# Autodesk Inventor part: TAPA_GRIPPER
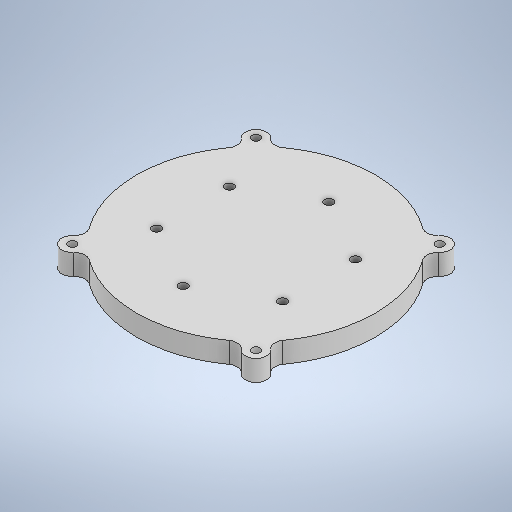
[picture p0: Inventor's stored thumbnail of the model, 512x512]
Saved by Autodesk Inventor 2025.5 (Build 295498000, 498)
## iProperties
Created: 2026-10
Part Number: TAPA_GRIPPER
Material: Genérico
Document SubType Name: Modeling
Designer: Luis MuÃ±oz
Density: 1 g/cm^3
Appearance: Valor por defecto
Project: TESIS 2 - Plataforma mecatrÃ³nica preventiva desacoplada
Description: Carcasa del módulo electrónico
Material_Fabricacion: PLA
Author: Luis M
Title: Carcasa del mÃ³dulo electrÃ³nico
Revision Number: 00
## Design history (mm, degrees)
sketch "Boceto1"
  geometry: L1 (5.6, 22)-(-5.6, 22); L2 (-5.6, 22)-(-5.6, -22); L3 (-5.6, -22)-(5.6, -22); L4 (5.6, -22)-(5.6, 22); L5 (5.6, 22)-(-5.6, -22); L6 (-5.6, 22)-(5.6, -22); L7 (0, 0)-(35, 0); L8 (35, 0)-(35, 40); L9 (35, 40)-(0, 40); L10 (0, 40)-(0, 0); L11 (35, 40)-(-27, 40); L12 (-27, 40)-(-27, -40); L13 (-27, -40)-(35, -40); L14 (35, -40)-(35, 40); C1 r 1.55 at (0, 0); C2 r 1.55 at (5.6, -22); C3 r 1.55 at (-5.6, -22); C4 r 1.55 at (5.6, 22); C5 r 1.55 at (-5.6, 22); C6 r 60.5 at (0, 0); C7 r 62.5 at (0, 0); C8 r 1.55 at (35, -40); C9 r 1.55 at (35, 40); C10 r 1.55 at (-27, 40); C11 r 1.55 at (-27, -40); 1 further point
  constraints: 28 end point, 11 centre point, 11 coincident, 6 parallel, 3 horizontal, 3 perpendicular, 2 midpoint
  dimensions: "d0" = 44 distance of L3.end L1.start; "d1" = 11.2 distance of L1.start L1.end; "d2" = 3.1 diameter of C1; "d3" = 3.1 diameter of C2; "d4" = 3.1 diameter of C3; "d5" = 3.1 diameter of C4; "d6" = 3.1 diameter of C5; "d7" = 121 diameter of C6; "d11" = 35 distance of L9.end L8.end; "d12" = 40 distance of L8.end L7.end; "d13" = 62 distance of L13.end L12.end; "d14" = 80 distance of L12.end L11.end; "d15" = 3.1 diameter of C8; "d16" = 3.1 diameter of C9; "d17" = 3.1 diameter of C10; "d18" = 3.1 diameter of C11
extrude "Extrusión1" new body sketch "Boceto1" distance "d9" = 6; taper "d10" = 0 deg
extrude "Extrusión2" cut sketch "Boceto1" distance "d19" = 5; taper "d20" = 0 deg
sketch "Boceto2"
  geometry: C1 r 1.55 at (27, -40) reference; C2 r 1.55 at (-35, -40) reference; C3 r 1.55 at (27, 40) reference; C4 r 1.55 at (-35, 40) reference; C5 r 60.5 at (0, 0) reference; C6 r 1.55 at (5.6, 22) reference; C7 r 1.55 at (5.6, -22) reference; C8 r 1.55 at (-5.6, -22) reference; C9 r 1.55 at (0, 0) reference; C10 r 1.55 at (-5.6, 22) reference; C11 r 57.5 at (0, 0); 1 further point
  constraints: 1 centre point, 1 coincident
  dimensions: "d21" = 115 diameter of C11
extrude "Extrusión3" join sketch "Boceto2" distance "d22" = 30; taper "d23" = 0 deg
sketch "Boceto5"
  geometry: L1 (-30, -57.5)-(-30, 57.5) reference; L2 (0, 57.5)-(0, -57.5) reference; L3 (0, 0)-(-12, 0); L4 (-7, 15)-(-17, 15); L5 (-17, 15)-(-17, -15); L6 (-17, -15)-(-7, -15); L7 (-7, -15)-(-7, 15); L8 (-7, 15)-(-17, -15); L9 (-17, 15)-(-7, -15); L10 (-12, 15)-(-12, -15)
  constraints: 16 end point, 4 midpoint, 2 horizontal, 2 parallel, 1 perpendicular
  dimensions: "d28" = 12 distance of L3.start L3.end; "d29" = 10 distance of L6.end L5.end; "d30" = 30 distance of L5.end L4.end
extrude "Extrusión5" cut sketch "Boceto5" stored distance "d31" = 181; taper "d32" = 0 deg
sketch "Boceto6"
  geometry: L1 (47.204, 44.298)-(42.204, 44.298); L2 (42.204, 44.298)-(42.204, -44.298); L3 (42.204, -44.298)-(47.204, -44.298); L4 (47.204, -44.298)-(47.204, 44.298); L5 (47.204, 44.298)-(42.204, -44.298); L6 (42.204, 44.298)-(47.204, -44.298); C1 r 60.5 at (0, 0) reference; C2 r 1.55 at (5.6, -22) reference; C3 r 1.55 at (5.6, 22) reference; C4 r 1.55 at (-5.6, 22) reference; C5 r 1.55 at (0, 0) reference; C6 r 1.55 at (-5.6, -22) reference; 6 further points
  constraints: 12 end point, 2 midpoint, 2 parallel, 1 horizontal, 1 perpendicular
  dimensions: "d33" = 5 distance of L3.end L2.end
extrude "Extrusión6" join sketch "Boceto6" distance "d34" = 25; taper "d35" = 0 deg
node "Plano de trabajo1"
sketch "Boceto7"
  geometry: L1 (87.646, 4.924)-(0.949, 4.924) reference; L2 (6.455, 0)-(82.14, 0) reference; L3 (6.455, 0)-(82.14, 0); L4 (82.14, 0)-(82.14, -10); L5 (82.14, -10)-(6.455, -10); L6 (6.455, -10)-(6.455, 0); L7 (44.298, -10)-(44.298, 0); L8 (66.798, -5)-(21.798, -5); C1 r 1.6 at (21.798, -5); C2 r 1.6 at (66.798, -5); 11 further points; 3 other entities
  constraints: 12 end point, 4 midpoint, 2 centre point, 2 coincident, 2 horizontal, 2 parallel, 1 perpendicular, 4 other
  dimensions: "d37" = 10 distance of L3.end L4.end; "d38" = 45 distance of L8.start L8.end; "d39" = 3.2 diameter of C1; "d40" = 3.2 diameter of C2
extrude "Extrusión7" join sketch "Boceto7" distance "d41" = 4; taper "d42" = 0 deg
fillet "Empalme3" dims "d45" = 4
sketch "Boceto8"
  geometry: L1 (-40, 50)-(40, 50); L2 (40, 50)-(40, -50); L3 (40, -50)-(-40, -50); L4 (-40, -50)-(-40, 50); L5 (-40, 50)-(40, -50); L6 (40, 50)-(-40, -50); L7 (48.099, 51.331)-(38.216, 40.784); L8 (38.216, 40.784)-(40.703, 59.935); L9 (40.703, 59.935)-(31.476, 46.348); L10 (47.613, -50.812)-(37.845, -40.388); L11 (30.656, -46.324)-(43.643, -62.557); L12 (-42.321, -62.318)-(-29.416, -43.314); L13 (-52.517, -56.045)-(-40, -42.688); L14 (-42.805, 60.306)-(-29.501, 46.108); L15 (-37.445, 39.961)-(-48.012, 51.238); C1 r 60.5 at (0, 0) reference; C2 r 57.5 at (0, 0) reference; C3 r 1.55 at (0, 0) reference; C4 r 2 at (40, 50); C5 r 2 at (40, -50); C6 r 2 at (-40, -50); C7 r 2 at (-40, 50); C8 r 5 at (40, 50); C9 r 5 at (40, -50); C10 r 5 at (-40, -50); C11 r 5 at (-40, 50); 18 further points
  constraints: 30 end point, 8 centre point, 8 coincident, 8 tangent, 6 line through centre, 3 parallel, 2 midpoint, 1 horizontal, 1 perpendicular, 1 point on line
  dimensions: "d46" = 80 distance of L2.end L3.end; "d47" = 100 distance of L1.end L2.end; "d48" = 4 diameter of C4; "d49" = 4 diameter of C5; "d50" = 4 diameter of C6; "d51" = 4 diameter of C7; "d52" = 10 diameter of C8; "d53" = 10 diameter of C9; "d54" = 10 diameter of C10; "d55" = 10 diameter of C11
extrude "Extrusión8" join sketch "Boceto8" distance "d56" = 10; taper "d57" = 0 deg
sketch "Boceto11"
  geometry: L1 (41.368, 44.147)-(43.649, 46.581) reference; L2 (35.864, 52.809)-(33.99, 50.05) reference; L3 (-33.502, 50.377)-(-36.351, 53.419) reference; L4 (-43.649, 46.581)-(-41.368, 44.147) reference; L5 (-41.368, -44.147)-(-43.649, -46.581) reference; L6 (-35.864, -52.809)-(-33.99, -50.05) reference; L7 (33.76, -50.204)-(36.096, -53.123) reference; L8 (43.649, -46.581)-(41.368, -44.147) reference; C1 r 40 at (0, 0); C2 r 57.5 at (0, 0); C3 r 81.97 at (6.395, 2.433); C4 r 2 at (40, 50) reference; C5 r 2 at (40, -50) reference; C6 r 2 at (-40, 50) reference; C7 r 2 at (-40, -50) reference; C8 r 57.5 at (0, 0) reference; A1 r 60.5 centre (0, 0) between (41.368, -44.147) and (41.368, 44.147) reference; A2 r 60.5 centre (0, 0) between (41.368, -44.147) and (41.368, 44.147) reference; A3 r 5 centre (40, 50) between (43.649, 46.581) and (35.864, 52.809) reference; A4 r 60.5 centre (0, 0) between (33.99, 50.05) and (-33.502, 50.377) reference; A5 r 5 centre (-40, 50) between (-36.351, 53.419) and (-43.649, 46.581) reference; A6 r 60.5 centre (0, 0) between (-41.368, 44.147) and (-41.368, -44.147) reference; A7 r 5 centre (-40, -50) between (-43.649, -46.581) and (-35.864, -52.809) reference; A8 r 60.5 centre (0, 0) between (-33.99, -50.05) and (33.76, -50.204) reference; A9 r 5 centre (40, -50) between (36.096, -53.123) and (43.649, -46.581) reference; A10 r 60.5 centre (0, 0) between (41.368, 44.147) and (33.99, 50.05) reference; A11 r 60.5 centre (0, 0) between (33.76, -50.204) and (41.368, -44.147) reference; A12 r 60.5 centre (0, 0) between (-41.368, -44.147) and (-33.99, -50.05) reference; A13 r 60.5 centre (0, 0) between (-33.502, 50.377) and (-41.368, 44.147) reference; 1 further point
  constraints: 3 centre point, 2 coincident
  dimensions: "d60" = 80 diameter of C1; "d61" = 115 diameter of C2
  node "Contorno proyectado8"
extrude "Extrusión9" cut sketch "Boceto11" distance "d62" = 78.5; taper "d63" = 0 deg
extrude "Extrusión10" join sketch "Boceto11" distance "d64" = 50; taper "d65" = 0 deg
sketch "Boceto12"
  geometry: C1 r 57.5 at (0, 0) reference; C2 r 1.55 at (27, -40) reference; C3 r 1.55 at (-35, -40) reference; C4 r 1.55 at (27, 40) reference; C5 r 1.55 at (-35, 40) reference; C6 r 1.55 at (5.6, 22) reference; C7 r 1.55 at (5.6, -22) reference; C8 r 1.55 at (-5.6, -22) reference; C9 r 1.55 at (0, 0) reference; C10 r 1.55 at (-5.6, 22) reference; 1 further point
extrude "Extrusión11" join sketch "Boceto12" stored distance "d66" = 50; taper "d67" = 0 deg
sketch "Boceto13"
  geometry: C1 r 1.6 at (17, 42); C2 r 1.6 at (35, -30); C3 r 1.6 at (-30, 35); C4 r 1.6 at (-30, -35); C5 r 57.5 at (0, 0) reference; C6 r 1.55 at (5.6, 22) reference; C7 r 1.55 at (5.6, -22) reference; C8 r 1.55 at (-5.6, -22) reference; C9 r 1.55 at (0, 0) reference; C10 r 1.55 at (-5.6, 22) reference; 1 further point
  constraints: 4 centre point
  dimensions: "d68" = 3.2 diameter of C1; "d69" = 3.2 diameter of C2; "d70" = 3.2 diameter of C3; "d71" = 3.2 diameter of C4; "d72" = 17 horizontal distance of point (0, 0) C1.centre; "d73" = 42 vertical distance of C1.centre point (0, 0); "d74" = 35 horizontal distance of point (0, 0) C2.centre; "d75" = 30 vertical distance of point (0, 0) C2.centre; "d76" = 35 vertical distance of point (0, 0) C4.centre; "d77" = 35 vertical distance of C3.centre point (0, 0); "d78" = 30 horizontal distance of point (0, 0) C3.centre; "d79" = 30 horizontal distance of C4.centre point (0, 0)
extrude "Extrusión12" cut sketch "Boceto13" distance "d80" = 65.25; taper "d81" = 0 deg
sketch "Boceto14"
  geometry: L1 (24.4, -14.4)-(-24.4, -14.4); L2 (24.4, 14.4)-(-24.1, 14.3); C1 r 1.6 at (24.4, 14.4); C2 r 1.6 at (24.4, -14.4); C3 r 1.6 at (-24.4, -14.4); C4 r 1.6 at (-24.1, 14.3); 1 further point
  constraints: 4 centre point, 4 end point, 1 horizontal
  dimensions: "d82" = 3.2 diameter of C1; "d83" = 3.2 diameter of C2; "d84" = 3.2 diameter of C3; "d85" = 3.2 diameter of C4; "d86" = 48.8 distance of L1.end L1.start; "d87" = 48.5 horizontal distance of L2.start L2.end; "d88" = 28.8 distance of L2.start L1.start; "d89" = 28.7 vertical distance of L2.end L1.end; "d90" = 0 horizontal distance of L2.start L1.start; "d91" = 24.4 horizontal distance of point (0, 0) L2.start; "d92" = 14.4 distance from line of L1 point (0, 0)
extrude "Extrusión13" cut sketch "Boceto14" distance "d93" = 111; taper "d94" = 0 deg
sketch "Boceto15"
  geometry: L1 (38.204, 46.912)-(38.204, -46.912) reference; C1 r 1.6 at (-24.4, 14.4) reference; C2 r 1.6 at (24.4, -14.4) reference; C3 r 1.6 at (-24.1, -14.3) reference; C4 r 1.6 at (24.4, 14.4) reference; C5 r 1.6 at (-30, -35) reference; C6 r 1.6 at (17, -42) reference; C7 r 1.6 at (-30, 35) reference; C8 r 1.6 at (35, 30) reference; C9 r 1.55 at (-5.6, -22) reference; C10 r 1.55 at (0, 0) reference; C11 r 1.55 at (-5.6, 22) reference; C12 r 1.55 at (5.6, 22) reference; C13 r 1.55 at (5.6, -22) reference; C14 r 2.75 at (24.4, 14.4); C15 r 2.75 at (24.4, -14.4); C16 r 2.75 at (-24.1, -14.3); C17 r 2.75 at (-24.4, 14.4); A1 r 60.5 centre (0, 0) between (38.204, 46.912) and (38.204, -46.912) reference; 1 further point
  constraints: 4 centre point, 4 coincident
  dimensions: "d95" = 5.5 diameter of C14; "d96" = 5.5 diameter of C15; "d97" = 5.5 diameter of C16; "d98" = 5.5 diameter of C17
extrude "Extrusión14" cut sketch "Boceto15" distance "d99" = 3; taper "d100" = 0 deg
sketch "Boceto16"
  geometry: C1 r 1.6 at (-24.4, -14.4) reference; C2 r 1.6 at (24.4, 14.4) reference; C3 r 1.6 at (-24.1, 14.3) reference; C4 r 1.6 at (24.4, -14.4) reference; C5 r 1.6 at (-30, 35) reference; C6 r 1.6 at (17, 42) reference; C7 r 1.6 at (-30, -35) reference; C8 r 1.6 at (35, -30) reference; C9 r 57.5 at (0, 0) reference; C10 r 1.55 at (5.6, 22) reference; C11 r 1.55 at (5.6, -22) reference; C12 r 1.55 at (-5.6, -22) reference; C13 r 1.55 at (0, 0) reference; C14 r 1.55 at (-5.6, 22) reference; C15 r 52.5 at (0, 0); C16 r 57.5 at (0, 0); C17 r 60.5 at (0, 0); 1 further point
  constraints: 3 centre point, 3 coincident, 1 concentric
  dimensions: "d101" = 105 diameter of C15
  node "Contorno proyectado12"
extrude "Extrusión15" cut sketch "Boceto16" stored distance "d102" = 76.75; taper "d103" = 0 deg
extrude "Extrusión16" join sketch "Boceto16" stored distance "d104" = 10; taper "d105" = 0 deg
sketch "Boceto17"
  geometry: 1 further point
sketch "Boceto18"
  geometry: L1 (-4.924, -1.096)-(-4.924, -0.949) reference; L2 (-5.077, -5.245)-(-5.077, -0.949) reference; L3 (0, -11.464)-(0, -77.132) reference; L4 (-5.077, -87.646)-(-5.077, -83.35) reference; L5 (-4.924, -87.646)-(-4.924, -87.499) reference; L6 (10, -82.14)-(0, -82.14) reference; L7 (10, -6.455)-(10, -82.14) reference; L8 (0, -6.455)-(10, -6.455) reference; L9 (0, -6.455)-(-5.077, -5.245); L10 (0, -82.14)-(-5.077, -83.35); C1 r 1.6 at (5, -21.798) reference; C2 r 1.6 at (5, -66.798) reference; 8 further points; 5 other entities
  constraints: 4 end point, 6 other
extrude "Extrusión17" cut sketch "Boceto18" distance "d106" = 10; taper "d107" = 0 deg
fillet "Empalme6" dims "d108" = 2
fillet "Empalme7" dims "d109" = 3
fillet "Empalme8" dims "d110" = 2
sketch "Boceto19" dims "d111" = 125
  geometry: L1 (0, 0)-(0, -46.545); L2 (44.194, -44.194)-(0, 0); L3 (52.406, 44.619)-(36.299, 30.905); L4 (36.299, 30.905)-(30.615, 35.958); L5 (30.615, 35.958)-(44.046, 51.733); L6 (49.862, -42.453)-(38.677, -32.93); L7 (38.677, -32.93)-(32.252, -37.881); L8 (32.252, -37.881)-(47.476, -55.761); L9 (-49.391, -58.011)-(-32.872, -38.609); L10 (-32.872, -38.609)-(-38.251, -32.567); L11 (-38.251, -32.567)-(-52.984, -45.111); L12 (-45.129, 53.005)-(-31.106, 36.534); L13 (-31.106, 36.534)-(-34.122, 29.052); L14 (-34.122, 29.052)-(-50.916, 43.35); C1 r 57.5 at (0, 0) reference; C2 r 52.5 at (0, 0) reference; C3 r 1.55 at (0, 0) reference; C4 r 2 at (44.194, -44.194); C5 r 2 at (44.194, 44.194); C6 r 2 at (-44.194, 44.194); C7 r 2 at (-44.194, -44.194); C8 r 5 at (44.194, 44.194); C9 r 5 at (44.194, -44.194); C10 r 5 at (-44.194, -44.194); C11 r 5 at (-44.194, 44.194); 18 further points
  constraints: 28 end point, 11 tangent, 8 centre point, 8 line through centre, 5 coincident, 1 vertical, 12 other
  dimensions: "d112" = 4 diameter of C4; "d115" = 360 deg dimension on point (0, 0) L2.start (derived); "d117" = 45 deg angle of L2 L1; "d118" = 10 diameter of C9
extrude "Extrusión18" join sketch "Boceto19" distance "d119" = 10; taper "d120" = 0 deg
fillet "Empalme9" dims "d121" = 5
sketch "Boceto20"
  geometry: C1 r 87.199 at (0, 9.569); 1 further point
  constraints: 1 centre point
extrude "Extrusión19" cut sketch "Boceto20" distance "d122" = 111.75; taper "d123" = 0 deg
sketch "Boceto21"
  geometry: C1 r 2 at (-44.194, -44.194) reference; C2 r 2 at (44.194, -44.194) reference; C3 r 2 at (-44.194, 44.194) reference; C4 r 2 at (44.194, 44.194) reference; C5 r 52.5 at (0, 0) reference; A1 r 57.5 centre (0, 0) between (46.623, -33.654) and (46.623, 33.654) reference; A2 r 5 centre (50.677, 36.58) between (47.436, 40.387) and (46.623, 33.654) reference; A3 r 5 centre (44.194, 44.194) between (47.436, 40.387) and (40.387, 47.436) reference; A4 r 5 centre (36.58, 50.677) between (33.654, 46.623) and (40.387, 47.436) reference; A5 r 57.5 centre (0, 0) between (33.654, 46.623) and (-33.654, 46.623) reference; A6 r 5 centre (-36.58, 50.677) between (-40.387, 47.436) and (-33.654, 46.623) reference; A7 r 5 centre (-44.194, 44.194) between (-40.387, 47.436) and (-47.436, 40.387) reference; A8 r 5 centre (-50.677, 36.58) between (-46.623, 33.654) and (-47.436, 40.387) reference; A9 r 57.5 centre (0, 0) between (-46.623, 33.654) and (-46.623, -33.654) reference; A10 r 5 centre (-50.677, -36.58) between (-47.436, -40.387) and (-46.623, -33.654) reference; A11 r 5 centre (-44.194, -44.194) between (-47.436, -40.387) and (-40.387, -47.436) reference; A12 r 5 centre (-36.58, -50.677) between (-33.654, -46.623) and (-40.387, -47.436) reference; A13 r 57.5 centre (0, 0) between (-33.654, -46.623) and (33.654, -46.623) reference; A14 r 5 centre (36.58, -50.677) between (40.387, -47.436) and (33.654, -46.623) reference; A15 r 5 centre (44.194, -44.194) between (40.387, -47.436) and (47.436, -40.387) reference; A16 r 5 centre (50.677, -36.58) between (46.623, -33.654) and (47.436, -40.387) reference; 1 further point
extrude "Extrusión20" join sketch "Boceto21" stored distance "d124" = 111.75; taper "d125" = 0 deg
sketch "Boceto22" dims "d126" = 70
  geometry: L1 (-44.194, -44.194)-(44.194, 44.194); L2 (44.194, 44.194)-(57.5, 0); L3 (-57.5, 0)-(57.5, 0); C1 r 2 at (44.194, 44.194) reference; C2 r 2 at (44.194, -44.194) reference; C3 r 2 at (-44.194, -44.194) reference; C4 r 2 at (-44.194, 44.194) reference; C5 r 2.1 at (0, 35); C6 r 2.1 at (-30.311, 17.5); C7 r 2.1 at (-30.311, -17.5); C8 r 2.1 at (0, -35); C9 r 2.1 at (30.311, -17.5); C10 r 2.1 at (30.311, 17.5); A1 r 5 centre (-44.194, 44.194) between (-40.387, 47.436) and (-47.436, 40.387) reference; A2 r 5 centre (-50.677, 36.58) between (-46.623, 33.654) and (-47.436, 40.387) reference; A3 r 57.5 centre (0, 0) between (-46.623, 33.654) and (-46.623, -33.654) reference; A4 r 5 centre (-50.677, -36.58) between (-47.436, -40.387) and (-46.623, -33.654) reference; A5 r 5 centre (-44.194, -44.194) between (-47.436, -40.387) and (-40.387, -47.436) reference; A6 r 5 centre (-36.58, -50.677) between (-33.654, -46.623) and (-40.387, -47.436) reference; A7 r 57.5 centre (0, 0) between (-33.654, -46.623) and (33.654, -46.623) reference; A8 r 5 centre (36.58, -50.677) between (40.387, -47.436) and (33.654, -46.623) reference; A9 r 5 centre (44.194, -44.194) between (40.387, -47.436) and (47.436, -40.387) reference; A10 r 5 centre (50.677, -36.58) between (46.623, -33.654) and (47.436, -40.387) reference; A11 r 57.5 centre (0, 0) between (46.623, -33.654) and (46.623, 33.654) reference; A12 r 5 centre (50.677, 36.58) between (47.436, 40.387) and (46.623, 33.654) reference; A13 r 5 centre (44.194, 44.194) between (47.436, 40.387) and (40.387, 47.436) reference; A14 r 5 centre (36.58, 50.677) between (33.654, 46.623) and (40.387, 47.436) reference; A15 r 57.5 centre (0, 0) between (33.654, 46.623) and (-33.654, 46.623) reference; A16 r 5 centre (-36.58, 50.677) between (-40.387, 47.436) and (-33.654, 46.623) reference; 2 further points
  constraints: 6 centre point, 6 end point, 2 midpoint, 2 point on circle, 1 horizontal, 1 vertical alignment, 15 other
  dimensions: "d127" = 4.2 diameter of C5; "d130" = 360 deg dimension on point (0, 0) C5.centre (derived)
extrude "Extrusión21" cut sketch "Boceto22" distance "d132" = 31.75; taper "d133" = 0 deg
node "Sólido1"
node "Contorno proyectado1"
node "Contorno proyectado3"
node "Contorno proyectado4"
node "Contorno proyectado5"
node "Contorno proyectado6"
node "Contorno proyectado9"
node "Contorno proyectado10"
node "Contorno proyectado11"
node "Contorno proyectado13"
node "Contorno proyectado14"
node "Boceto - Patrón circular1" dims "d115" = 360 deg (derived)
node "Contorno proyectado15"
node "Contorno proyectado16"
node "Boceto - Patrón circular2" dims "d130" = 360 deg (derived)
other parameters: "d36" = -100 deg
